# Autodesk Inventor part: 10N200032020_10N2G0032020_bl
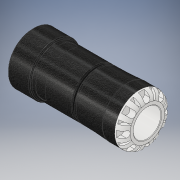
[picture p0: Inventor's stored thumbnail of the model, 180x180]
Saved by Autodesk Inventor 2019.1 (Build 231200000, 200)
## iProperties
Created: 2016-12
Part Number: 10N200032020_10N2G0032020_bl
Material: PVC-Piping
Description: PLASSON MALE ADAPTOR 32X2" SERIES 1
Document SubType Name: Modeling
Designer: KIM
Mass: 61.7504 g
Surface Area: 140.097 cm^2
Volume: 44.1074 cm^3
Density: 1.4 g/cm^3
Appearance: Black Cast
Author: KIM
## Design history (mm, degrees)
derived "10N20.ipt"
feature "Solid1::10N20.ipt" dims "ScaleForDerivedMember" = 10
tag "TaggingFeature1"
body "Solid1"
other parameters: "d0" = 133 [user parameter], "d1" = 23.1 [user parameter], "d2" = 32 [user parameter], "d4" = 58 [user parameter], "d6" = 55 [user parameter], "d8" = 55.1 [user parameter], "d13" = 7.2 [user parameter], "d14" = 7.2 [user parameter], "d15" = 0 [user parameter], "d17" = 360 deg [user parameter], "d19" = 8 deg [user parameter], "d20" = 0.64 [user parameter], "d21" = 0.64 [user parameter], "d22" = 8 deg [user parameter], "d24" = 0 [user parameter], "d26" = 360 deg [user parameter], "d32" = 0.925 [user parameter], "d33" = 5.8 [user parameter], "d34" = 59.614 [user parameter], "d35" = 4 [user parameter], "d38" = 26 [user parameter], "d39" = 1.78842 [user parameter], "d42" = 11.2 [user parameter], "d43" = 7.36 [user parameter], "d45" = 14.112 [user parameter], "d46" = 0 [user parameter], "d59" = 360 deg [user parameter], "d61" = 9.52 [user parameter], "d62" = 0.64 [user parameter], "d64" = 0 [user parameter], "d65" = 0.58 [user parameter], "d69" = 2 [user parameter], "d70" = 1.995 [user parameter], "d71" = 3 [user parameter], "d73" = 1 [user parameter], "d_" = 32 [user parameter], "E_" = 58 [user parameter], "H_" = 133 [user parameter], "l_" = 55 [user parameter], "R_" = 59.614 [user parameter], "l_2" = 26 [user parameter], "d9" = 9 [user parameter], "d11" = 58 [user parameter]
